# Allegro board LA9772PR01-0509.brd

Outline 275.55 x 178.7 mm; copper layers: TOP, GND1, IN1, VCC, IN2, IN3, GND2, IN4, GND3, BOTTOM. Coordinates in mm from the lower left corner of the outline.

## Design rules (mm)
net group AUDIO: nets PCH_AZ_CODEC_SDIN0 SPKR
net group BLUE_CRT: nets BLUE_CRT BLUE_CRT_L
net group CLK_BUF_DMI: nets CLK_BUF_DMI CLK_BUF_DMI#
net group CLK_CPU_DMI: nets CLK_CPU_DMI CLK_CPU_DMI#
net group CLK_CPU_ITP: nets CLK_CPU_ITP CLK_XDP
net group CLK_CPU_ITP#: nets CLK_CPU_ITP# CLK_XDP#
net group CLK_PCIE_CARD: nets CLK_PCIE_CARD CLK_PCIE_CARD#
net group CLK_PCIE_MINI2: nets CLK_PCIE_MINI2 CLK_PCIE_MINI2#
net group CPU_DPLL: nets CLK_CPU_DPLL CLK_CPU_DPLL#
net group CPU_EDP_AUX: nets CPU_EDP_AUX CPU_EDP_AUX#
net group CPU_EDP_LANE_N0: nets CPU_EDP_LANE_N0 CPU_EDP_LANE_P0
net group CPU_EDP_LANE_N1: nets CPU_EDP_LANE_N1 CPU_EDP_LANE_P1
net group CPU_SSC_DPLL: nets CLK_CPU_SSC_DPLL CLK_CPU_SSC_DPLL#
net group DIFFPAIR0: nets LAN_TX0+ LAN_TX0-
net group DIFFPAIR1: nets PCIE_PRX_WPANTX_N6 PCIE_PRX_WPANTX_P6
net group DIFFPAIR3: nets PCIE_PTX_WPANRX_N6_C PCIE_PTX_WPANRX_P6_C
net group DMI_CTX_PRX_N2: nets DMI_CTX_PRX_N2 DMI_CTX_PRX_P2
net group DP_DDC-DPD_DOCK_AUX: nets DPD_DOCK_AUX DPD_DOCK_AUX#
net group DP_DDC-MB_DP_RP_AUX: nets MB_DP_RP_AUX MB_DP_RP_AUX#
net group DP_DDC-NUX_AUX: nets MUX_AUX MUX_AUX#
net group DP_DPC_DOCK_AUX: nets DPC_DOCK_AUX DPC_DOCK_AUX#
net group DP_DPC_DOCK_SW_AUX: nets DPC_DOCK_SW_AUX DPC_DOCK_SW_AUX#
net group DP_LAN_TX1+R: nets LAN_TX1+R LAN_TX1-R
net group DP_LAN_TX2+R: nets LAN_TX2+R LAN_TX2-R
net group DP_LAN_TX3+R: nets LAN_TX3+R LAN_TX3-R
net group DP_PCH_DDPD_CTRL: nets PCH_DDPD_CTRLCLK PCH_DDPD_CTRLDATA
net group DP_PCIE_PRX_WLANTX_3: nets PCIE_PRX_WLANTX_N3 PCIE_PRX_WLANTX_P3
net group DP_PCIE_PTX_EXPRX_7: nets PCIE_PTX_EXPRX_N7 PCIE_PTX_EXPRX_P7
net group DP_USB3R3: nets USB3RN3 USB3RP3
net group DP_USB3R5: nets USB3RN5 USB3RP5
net group DP_USB3R6: nets USB3RN6 USB3RP6
net group DP_USB3T3: nets USB3TN3 USB3TP3
net group DP_USB3T5: nets USB3TN5 USB3TP5
net group DP_USB3T6: nets USB3TN6 USB3TP6
net group DP_VCC_VSS-SENSE: nets VCCSENSE VSSSENSE
net group DPD_CPU_LANE_N0: nets DPD_CPU_LANE_N0 DPD_CPU_LANE_N0_C
net group DPD_CPU_LANE_N1: nets DPD_CPU_LANE_N1 DPD_CPU_LANE_N1_C
net group DPD_CPU_LANE_N2: nets DPD_CPU_LANE_N2 DPD_CPU_LANE_N2_C
net group DPD_CPU_LANE_N3: nets DPD_CPU_LANE_N3 DPD_CPU_LANE_N3_C
net group DPD_CPU_LANE_P0: nets DPD_CPU_LANE_P0 DPD_CPU_LANE_P0_C
net group DPD_CPU_LANE_P1: nets DPD_CPU_LANE_P1 DPD_CPU_LANE_P1_C
net group DPD_CPU_LANE_P2: nets DPD_CPU_LANE_P2 DPD_CPU_LANE_P2_C
net group DPD_CPU_LANE_P3: nets DPD_CPU_LANE_P3 DPD_CPU_LANE_P3_C
net group ESATA_PRX_DTX_N3_C: nets ESATA_PRX_DTX_N3_C SATA_PRX_DTX_N3
net group ESATA_PRX_DTX_P3_C: nets ESATA_PRX_DTX_P3_C SATA_PRX_DTX_P3
net group ESATA_PTX_DRX_N3_C: nets ESATA_PTX_DRX_N3_C SATA_PTX_DRX_N3
net group ESATA_PTX_DRX_P3_C: nets ESATA_PTX_DRX_P3_C SATA_PTX_DRX_P3
net group FDI-SINGLE: nets FDI_CSYNC FDI_INT
net group GREEN_CRT: nets GREEN_CRT GREEN_CRT_L
net group HDMI_I2C: nets HDMI_SCL_SINK HDMI_SDA_SINK
net group HSYNC: nets HSYNC PCH_CRT_HSYNC
net group HSYNC_BUF: nets HSYNC_BUF HSYNC_L
net group LAN_SMBCLK: nets LAN_SMBCLK LAN_SMBDATA
net group LAN_TX0+: nets LAN_TX0+R LAN_TX0-R
net group LAN_TX1+R: nets LAN_TX1+ LAN_TX1-
net group LAN_TX2+R: nets LAN_TX2+ LAN_TX2-
net group LAN_TX3+R: nets LAN_TX3+ LAN_TX3-
net group MB_DP_RP_C_N0: nets MB_DP_RP_C_N0 MB_DP_RP_N0
net group MB_DP_RP_C_N1: nets MB_DP_RP_C_N1 MB_DP_RP_N1
net group MB_DP_RP_C_N2: nets MB_DP_RP_C_N2 MB_DP_RP_N2
net group MB_DP_RP_C_N3: nets MB_DP_RP_C_N3 MB_DP_RP_N3
net group MB_DP_RP_C_P0: nets MB_DP_RP_C_P0 MB_DP_RP_P0
net group MB_DP_RP_C_P1: nets MB_DP_RP_C_P1 MB_DP_RP_P1
net group MB_DP_RP_C_P2: nets MB_DP_RP_C_P2 MB_DP_RP_P2
net group MB_DP_RP_C_P3: nets MB_DP_RP_C_P3 MB_DP_RP_P3
net group MSATA_PRX_WANTX_N4_RP: nets MSATA_PRX_WANTX_N4_RP MSATA_PRX_WANTX_N4_RP_C
net group MSATA_PRX_WANTX_P4_RP: nets MSATA_PRX_WANTX_P4_RP MSATA_PRX_WANTX_P4_RP_C
net group MSATA_PTX_WANRX_N4_RP: nets MSATA_PTX_WANRX_N4_RP MSATA_PTX_WANRX_N4_RP_C
net group MSATA_PTX_WANRX_P4_RP: nets MSATA_PTX_WANRX_P4_RP MSATA_PTX_WANRX_P4_RP_C
net group MUX_D0: nets MUX_D0 MUX_D0_C
net group MUX_D0#: nets MUX_D0# MUX_D0#_C
net group MUX_D1: nets MUX_D1 MUX_D1_C
net group MUX_D1#: nets MUX_D1# MUX_D1#_C
net group MUX_D2: nets MUX_D2 MUX_D2_C
net group MUX_D2#: nets MUX_D2# MUX_D2#_C
net group MUX_D3: nets MUX_D3 MUX_D3_C
net group MUX_D3#: nets MUX_D3# MUX_D3#_C
net group MXM_DPC_AUX: nets MXM_DPC_AUX MXM_DPC_AUX_C
net group MXM_DPC_AUX#: nets MXM_DPC_AUX# MXM_DPC_AUX#_C
net group MXM_DPC_N0: nets MXM_DPC_N0 MXM_DPC_N0_C
net group MXM_DPC_N1: nets MXM_DPC_N1 MXM_DPC_N1_C
net group MXM_DPC_N2: nets MXM_DPC_N2 MXM_DPC_N2_C
net group MXM_DPC_N3: nets MXM_DPC_N3 MXM_DPC_N3_C
net group MXM_DPC_P0: nets MXM_DPC_P0 MXM_DPC_P0_C
net group MXM_DPC_P1: nets MXM_DPC_P1 MXM_DPC_P1_C
net group MXM_DPC_P2: nets MXM_DPC_P2 MXM_DPC_P2_C
net group MXM_DPC_P3: nets MXM_DPC_P3 MXM_DPC_P3_C
net group MXM_MB_DP_N0: nets MXM_MB_DP_N0 MXM_MB_DP_N0_C
net group MXM_MB_DP_N1: nets MXM_MB_DP_N1 MXM_MB_DP_N1_C
net group MXM_MB_DP_N2: nets MXM_MB_DP_N2 MXM_MB_DP_N2_C
net group MXM_MB_DP_N3: nets MXM_MB_DP_N3 MXM_MB_DP_N3_C
net group MXM_MB_DP_P0: nets MXM_MB_DP_P0 MXM_MB_DP_P0_C
net group MXM_MB_DP_P1: nets MXM_MB_DP_P1 MXM_MB_DP_P1_C
net group MXM_MB_DP_P2: nets MXM_MB_DP_P2 MXM_MB_DP_P2_C
net group MXM_MB_DP_P3: nets MXM_MB_DP_P3 MXM_MB_DP_P3_C
net group PBAT_SMBCLK: nets PBAT_SMBCLK Z4304
net group PBAT_SMBDAT: nets PBAT_SMBDAT Z4305
net group PCH_AZ_BITCLK: nets PCH_AZ_BITCLK PCH_AZ_CODEC_BITCLK
net group PCH_AZ_CODEC_RST#: nets PCH_AZ_CODEC_RST# PCH_AZ_RST#
net group PCH_AZ_CODEC_SDOUT: nets PCH_AZ_CODEC_SDOUT PCH_AZ_SDOUT
net group PCH_AZ_CODEC_SYNC: nets PCH_AZ_CODEC_SYNC PCH_AZ_SYNC
net group PCH_CL_CLK1: nets PCH_CL_CLK1 PCH_CL_DATA1
net group PCH_CRT_VSYNC: nets PCH_CRT_VSYNC VSYNC
net group PCH_DDPD_AUX: nets PCH_DDPD_AUX PCH_DDPD_AUX_C
net group PCH_DDPD_AUX#: nets PCH_DDPD_AUX# PCH_DDPD_AUX#_C
net group PCIE_EXP: nets CLK_PCIE_EXP CLK_PCIE_EXP#
net group PCIE_MINI1: nets CLK_PCIE_MINI1 CLK_PCIE_MINI1#
net group PCIE_PRX_GLANTX_N2: nets PCIE_PRX_GLANTX_N2 PCIE_PRX_GLANTX_N2_C
net group PCIE_PRX_GLANTX_P2: nets PCIE_PRX_GLANTX_P2 PCIE_PRX_GLANTX_P2_C
net group PCIE_PTX_GLANRX_N2: nets PCIE_PTX_GLANRX_N2 PCIE_PTX_GLANRX_N2_C
net group PCIE_PTX_GLANRX_P2: nets PCIE_PTX_GLANRX_P2 PCIE_PTX_GLANRX_P2_C
net group PCIE_PTX_WLANRX_N3: nets PCIE_PTX_WLANRX_N3 PCIE_PTX_WLANRX_N3_C
net group PCIE_PTX_WLANRX_P3: nets PCIE_PTX_WLANRX_P3 PCIE_PTX_WLANRX_P3_C
net group PCIE_SATA_PRX_WANTX_N4: nets PCIE_SATA_PRX_WANTX_N4 PCIE_SATA_PRX_WANTX_N4_C
net group PCIE_SATA_PRX_WANTX_P4: nets PCIE_SATA_PRX_WANTX_P4 PCIE_SATA_PRX_WANTX_P4_C
net group PCIE_SATA_PTX_WANRX_N4: nets PCIE_SATA_PTX_WANRX_N4 PCIE_SATA_PTX_WANRX_N4_C
net group PCIE_SATA_PTX_WANRX_P4: nets PCIE_SATA_PTX_WANRX_P4 PCIE_SATA_PTX_WANRX_P4_C
net group PECI_EC: nets PECI_EC PECI_EC_R
net group PEG_CRX_GTX_C_N0: nets PEG_CRX_GTX_C_N0 PEG_CRX_GTX_N0
net group PEG_CRX_GTX_C_N1: nets PEG_CRX_GTX_C_N1 PEG_CRX_GTX_N1
net group PEG_CRX_GTX_C_N2: nets PEG_CRX_GTX_C_N2 PEG_CRX_GTX_N2
net group PEG_CRX_GTX_C_N3: nets PEG_CRX_GTX_C_N3 PEG_CRX_GTX_N3
net group PEG_CRX_GTX_C_N4: nets PEG_CRX_GTX_C_N4 PEG_CRX_GTX_N4
net group PEG_CRX_GTX_C_N5: nets PEG_CRX_GTX_C_N5 PEG_CRX_GTX_N5
net group PEG_CRX_GTX_C_N6: nets PEG_CRX_GTX_C_N6 PEG_CRX_GTX_N6
net group PEG_CRX_GTX_C_N7: nets PEG_CRX_GTX_C_N7 PEG_CRX_GTX_N7
net group PEG_CRX_GTX_C_N8: nets PEG_CRX_GTX_C_N8 PEG_CRX_GTX_N8
net group PEG_CRX_GTX_C_N9: nets PEG_CRX_GTX_C_N9 PEG_CRX_GTX_N9
net group PEG_CRX_GTX_C_N10: nets PEG_CRX_GTX_C_N10 PEG_CRX_GTX_N10
net group PEG_CRX_GTX_C_N11: nets PEG_CRX_GTX_C_N11 PEG_CRX_GTX_N11
net group PEG_CRX_GTX_C_N12: nets PEG_CRX_GTX_C_N12 PEG_CRX_GTX_N12
net group PEG_CRX_GTX_C_N13: nets PEG_CRX_GTX_C_N13 PEG_CRX_GTX_N13
net group PEG_CRX_GTX_C_N14: nets PEG_CRX_GTX_C_N14 PEG_CRX_GTX_N14
net group PEG_CRX_GTX_C_N15: nets PEG_CRX_GTX_C_N15 PEG_CRX_GTX_N15
net group PEG_CRX_GTX_C_P0: nets PEG_CRX_GTX_C_P0 PEG_CRX_GTX_P0
net group PEG_CRX_GTX_C_P1: nets PEG_CRX_GTX_C_P1 PEG_CRX_GTX_P1
net group PEG_CRX_GTX_C_P2: nets PEG_CRX_GTX_C_P2 PEG_CRX_GTX_P2
net group PEG_CRX_GTX_C_P3: nets PEG_CRX_GTX_C_P3 PEG_CRX_GTX_P3
net group PEG_CRX_GTX_C_P4: nets PEG_CRX_GTX_C_P4 PEG_CRX_GTX_P4
net group PEG_CRX_GTX_C_P5: nets PEG_CRX_GTX_C_P5 PEG_CRX_GTX_P5
net group PEG_CRX_GTX_C_P6: nets PEG_CRX_GTX_C_P6 PEG_CRX_GTX_P6
net group PEG_CRX_GTX_C_P7: nets PEG_CRX_GTX_C_P7 PEG_CRX_GTX_P7
net group PEG_CRX_GTX_C_P8: nets PEG_CRX_GTX_C_P8 PEG_CRX_GTX_P8
net group PEG_CRX_GTX_C_P9: nets PEG_CRX_GTX_C_P9 PEG_CRX_GTX_P9
net group PEG_CRX_GTX_C_P10: nets PEG_CRX_GTX_C_P10 PEG_CRX_GTX_P10
net group PEG_CRX_GTX_C_P11: nets PEG_CRX_GTX_C_P11 PEG_CRX_GTX_P11
net group PEG_CRX_GTX_C_P12: nets PEG_CRX_GTX_C_P12 PEG_CRX_GTX_P12
net group PEG_CRX_GTX_C_P13: nets PEG_CRX_GTX_C_P13 PEG_CRX_GTX_P13
net group PEG_CRX_GTX_C_P14: nets PEG_CRX_GTX_C_P14 PEG_CRX_GTX_P14
net group PEG_CRX_GTX_C_P15: nets PEG_CRX_GTX_C_P15 PEG_CRX_GTX_P15
net group PEG_CTX_GRX_C_N0: nets PEG_CTX_GRX_C_N0 PEG_CTX_GRX_N0
net group PEG_CTX_GRX_C_N1: nets PEG_CTX_GRX_C_N1 PEG_CTX_GRX_N1
net group PEG_CTX_GRX_C_N2: nets PEG_CTX_GRX_C_N2 PEG_CTX_GRX_N2
net group PEG_CTX_GRX_C_N3: nets PEG_CTX_GRX_C_N3 PEG_CTX_GRX_N3
net group PEG_CTX_GRX_C_N4: nets PEG_CTX_GRX_C_N4 PEG_CTX_GRX_N4
net group PEG_CTX_GRX_C_N5: nets PEG_CTX_GRX_C_N5 PEG_CTX_GRX_N5
net group PEG_CTX_GRX_C_N6: nets PEG_CTX_GRX_C_N6 PEG_CTX_GRX_N6
net group PEG_CTX_GRX_C_N7: nets PEG_CTX_GRX_C_N7 PEG_CTX_GRX_N7
net group PEG_CTX_GRX_C_N8: nets PEG_CTX_GRX_C_N8 PEG_CTX_GRX_N8
net group PEG_CTX_GRX_C_N9: nets PEG_CTX_GRX_C_N9 PEG_CTX_GRX_N9
net group PEG_CTX_GRX_C_N10: nets PEG_CTX_GRX_C_N10 PEG_CTX_GRX_N10
net group PEG_CTX_GRX_C_N11: nets PEG_CTX_GRX_C_N11 PEG_CTX_GRX_N11
net group PEG_CTX_GRX_C_N12: nets PEG_CTX_GRX_C_N12 PEG_CTX_GRX_N12
net group PEG_CTX_GRX_C_N13: nets PEG_CTX_GRX_C_N13 PEG_CTX_GRX_N13
net group PEG_CTX_GRX_C_N14: nets PEG_CTX_GRX_C_N14 PEG_CTX_GRX_N14
net group PEG_CTX_GRX_C_N15: nets PEG_CTX_GRX_C_N15 PEG_CTX_GRX_N15
net group PEG_CTX_GRX_C_P0: nets PEG_CTX_GRX_C_P0 PEG_CTX_GRX_P0
net group PEG_CTX_GRX_C_P1: nets PEG_CTX_GRX_C_P1 PEG_CTX_GRX_P1
net group PEG_CTX_GRX_C_P2: nets PEG_CTX_GRX_C_P2 PEG_CTX_GRX_P2
net group PEG_CTX_GRX_C_P3: nets PEG_CTX_GRX_C_P3 PEG_CTX_GRX_P3
net group PEG_CTX_GRX_C_P4: nets PEG_CTX_GRX_C_P4 PEG_CTX_GRX_P4
net group PEG_CTX_GRX_C_P5: nets PEG_CTX_GRX_C_P5 PEG_CTX_GRX_P5
net group PEG_CTX_GRX_C_P6: nets PEG_CTX_GRX_C_P6 PEG_CTX_GRX_P6
net group PEG_CTX_GRX_C_P7: nets PEG_CTX_GRX_C_P7 PEG_CTX_GRX_P7
net group PEG_CTX_GRX_C_P8: nets PEG_CTX_GRX_C_P8 PEG_CTX_GRX_P8
net group PEG_CTX_GRX_C_P9: nets PEG_CTX_GRX_C_P9 PEG_CTX_GRX_P9
net group PEG_CTX_GRX_C_P10: nets PEG_CTX_GRX_C_P10 PEG_CTX_GRX_P10
net group PEG_CTX_GRX_C_P11: nets PEG_CTX_GRX_C_P11 PEG_CTX_GRX_P11
net group PEG_CTX_GRX_C_P12: nets PEG_CTX_GRX_C_P12 PEG_CTX_GRX_P12
net group PEG_CTX_GRX_C_P13: nets PEG_CTX_GRX_C_P13 PEG_CTX_GRX_P13
net group PEG_CTX_GRX_C_P14: nets PEG_CTX_GRX_C_P14 PEG_CTX_GRX_P14
net group PEG_CTX_GRX_C_P15: nets PEG_CTX_GRX_C_P15 PEG_CTX_GRX_P15
net group PSATA_PRX_DTX_N0: nets PSATA_PRX_DTX_N0 PSATA_PRX_DTX_N0_C
net group PSATA_PRX_DTX_P0: nets PSATA_PRX_DTX_P0 PSATA_PRX_DTX_P0_C
net group PSATA_PTX_DRX_N0: nets PSATA_PTX_DRX_N0 PSATA_PTX_DRX_N0_C
net group PSATA_PTX_DRX_P0: nets PSATA_PTX_DRX_P0 PSATA_PTX_DRX_P0_C
net group RED_CRT: nets RED_CRT RED_CRT_L
net group SATA_ODD_PRX_DTX_N1: nets SATA_ODD_PRX_DTX_N1 SATA_ODD_PRX_DTX_N1_C
net group SATA_ODD_PRX_DTX_P1: nets SATA_ODD_PRX_DTX_P1 SATA_ODD_PRX_DTX_P1_C
net group SATA_ODD_PTX_DRX_N1: nets SATA_ODD_PTX_DRX_N1 SATA_ODD_PTX_DRX_N1_C
net group SATA_ODD_PTX_DRX_P1: nets SATA_ODD_PTX_DRX_P1 SATA_ODD_PTX_DRX_P1_C
net group SATA_PRX_DKTX_N2: nets SATA_PRX_DKTX_N2 SATA_PRX_DKTX_N2_C
net group SATA_PRX_DKTX_P2: nets SATA_PRX_DKTX_P2 SATA_PRX_DKTX_P2_C
net group SATA_PTX_DKRX_N2: nets SATA_PTX_DKRX_N2 SATA_PTX_DKRX_N2_C
net group SATA_PTX_DKRX_P2: nets SATA_PTX_DKRX_P2 SATA_PTX_DKRX_P2_C
net group SCLK: nets SCLK VIDSCLK
net group SDA: nets SDA VIDSOUT
net group TMDSE_CON_CLK: nets TMDSE_CON_CLK TMDSE_RP_CLK
net group TMDSE_CON_CLK#: nets TMDSE_CON_CLK# TMDSE_RP_CLK#
net group TMDSE_CON_N0: nets TMDSE_CON_N0 TMDSE_RP_N0
net group TMDSE_CON_N1: nets TMDSE_CON_N1 TMDSE_RP_N1
net group TMDSE_CON_N2: nets TMDSE_CON_N2 TMDSE_RP_N2
net group TMDSE_CON_P0: nets TMDSE_CON_P0 TMDSE_RP_P0
net group TMDSE_CON_P1: nets TMDSE_CON_P1 TMDSE_RP_P1
net group TMDSE_CON_P2: nets TMDSE_CON_P2 TMDSE_RP_P2
net group USB3RN1: nets USB3RN1 USB3RN1_C
net group USB3RN1_RP: nets USB3_RX1_N_D- USB3RN1_RP
net group USB3RN2: nets USB3RN2 USB3RN2_C
net group USB3RN2_RP: nets USB3_RX2_N_D- USB3RN2_RP
net group USB3RP1: nets USB3RP1 USB3RP1_C
net group USB3RP1_RP: nets USB3_RX1_P_D+ USB3RP1_RP
net group USB3RP2: nets USB3RP2 USB3RP2_C
net group USB3RP2_RP: nets USB3_RX2_P_D+ USB3RP2_RP
net group USB3TN1: nets USB3TN1 USB3TN1_C
net group USB3TN2: nets USB3TN2 USB3TN2_C
net group USB3TP1: nets USB3TP1 USB3TP1_C
net group USB3TP2: nets USB3TP2 USB3TP2_C
net group USBP0_D+: nets USBP0_D+ USBP0_R_D+
net group USBP0_D-: nets USBP0_D- USBP0_R_D-
net group USBP1+: nets USBP1+ USBP1_D+
net group USBP1-: nets USBP1- USBP1_D-
net group USBP8+: nets USBP8+ USBP8_D+
net group USBP8-: nets USBP8- USBP8_D-
net group USBP12+: nets USBP12+ USBP12_D+
net group USBP12-: nets USBP12- USBP12_D-
net group VSYNC_BUF: nets VSYNC_BUF VSYNC_L
net group ALERT#: nets ALERT# H_CPU_SVIDALRT# VIDALERT_N
net group ASYNCHRONOUS: nets DDR3_DRAMRST#_CPU DDR3_DRAMRST#_R DDR_HVREF_RST_PCH H_CATERR# H_CPUPWRGD H_CPUPWRGD_XDP H_PM_SYNC H_PROCHOT# H_PROCHOT#_R H_THERMTRIP# PCH_JTAG_TCK PCH_JTAG_TMS PCH_PLTRST# PCH_PLTRST#_EC PM_DRAM_PWRGD RUNPWROK THERMATRIP2# XDP_RST#_R XDP_TCLK
net group ASYNCHRONOUS-S15: nets PEG_COMP
net group ASYNCHRONOUS-S20: nets DMI_RCOMP
net group CLK-SINGLE: nets CLK_PCH_14M
net group CLK-SINGLE-S15: nets CLK_80H CLK_PCI_LOOPBACK CLK_PCI_TPM CLK_SIO_14M JETWAY_14M JETWAY_CLK14M PCI_LOOPBACKOUT PCI_TPM_TCM PCLK_80H SIO_14M
net group CLK_SRC: nets CLK_PCIE_LAN CLK_PCIE_LAN# CLK_PCIE_MINI3 CLK_PCIE_MINI3# CLK_PCIE_VGA CLK_PCIE_VGA#
net group CONTROL LINK: nets PCH_CL_RST1#
net group CRT-DAC: nets BLUE_DOCK GREEN_DOCK MXM_CRT_BLU MXM_CRT_GRN MXM_CRT_RED PCH_CRT_BLU PCH_CRT_GRN PCH_CRT_RED RED_DOCK
net group CRT-SINGLE: nets CLK_DDC2_CRT CLK_DDC2_DOCK DAT_DDC2_CRT DAT_DDC2_DOCK
net group CRT-SYNC: nets HSYNC_DOCK MXM_CRT_HSYNC MXM_CRT_VSYNC VSYNC_DOCK
net group DDR_XDP_SMBCLK_R1: nets DDR_XDP_SMBCLK_R1 DDR_XDP_WAN_SMBCLK DDR_XDP_WAN_SMBCLK_R2
net group DDR_XDP_SMBDAT_R1: nets DDR_XDP_SMBDAT_R1 DDR_XDP_WAN_SMBDAT DDR_XDP_WAN_SMBDAT_R2
net group DDRA_D0: nets DDR_A_D0 DDR_A_D1 DDR_A_D4 DDR_A_D5
net group DDRA_D1: nets DDR_A_D10 DDR_A_D11 DDR_A_D12 DDR_A_D13
net group DDRA_D2: nets DDR_A_D16 DDR_A_D17 DDR_A_D18 DDR_A_D19 DDR_A_D20 DDR_A_D21 DDR_A_D22 DDR_A_D23
net group DDRA_D3: nets DDR_A_D24 DDR_A_D25 DDR_A_D26 DDR_A_D27 DDR_A_D28 DDR_A_D29 DDR_A_D30 DDR_A_D31
net group DDRA_D4: nets DDR_A_D32 DDR_A_D33 DDR_A_D36 DDR_A_D37
net group DDRA_D5: nets DDR_A_D40 DDR_A_D41 DDR_A_D42 DDR_A_D43 DDR_A_D44 DDR_A_D45 DDR_A_D46 DDR_A_D47
net group DDRA_D6: nets DDR_A_D50 DDR_A_D51 DDR_A_D54
net group DDRA_D7: nets DDR_A_D56 DDR_A_D57 DDR_A_D60 DDR_A_D61 DDR_A_D62 DDR_A_D63
net group DDRB_D0: nets DDR_B_D0 DDR_B_D1 DDR_B_D2 DDR_B_D3 DDR_B_D4 DDR_B_D5 DDR_B_D6 DDR_B_D7
net group DDRB_D1: nets DDR_B_D8 DDR_B_D9 DDR_B_D10 DDR_B_D12 DDR_B_D13 DDR_B_D14
net group DDRB_D2: nets DDR_B_D16 DDR_B_D17 DDR_B_D18 DDR_B_D19 DDR_B_D20 DDR_B_D21 DDR_B_D22 DDR_B_D23
net group DDRB_D3: nets DDR_B_D24 DDR_B_D25 DDR_B_D26 DDR_B_D27 DDR_B_D28 DDR_B_D29 DDR_B_D30 DDR_B_D31
net group DDRB_D4: nets DDR_B_D32 DDR_B_D33 DDR_B_D34 DDR_B_D35 DDR_B_D36 DDR_B_D37 DDR_B_D38 DDR_B_D39
net group DDRB_D5: nets DDR_B_D40 DDR_B_D41 DDR_B_D42 DDR_B_D43 DDR_B_D44 DDR_B_D45
net group DDRB_D6: nets DDR_B_D50 DDR_B_D51 DDR_B_D54 DDR_B_D55
net group DDRB_D7: nets DDR_B_D56 DDR_B_D57 DDR_B_D58 DDR_B_D59 DDR_B_D62 DDR_B_D63
net group DPC_DOCK_LANE_C_N0: nets DPC_DOCK_LANE_C_N0 DPC_DOCK_LANE_N0_R MXM_DPB_N0
net group DPC_DOCK_LANE_C_N1: nets DPC_DOCK_LANE_C_N1 DPC_DOCK_LANE_N1_R MXM_DPB_N1
net group DPC_DOCK_LANE_C_N2: nets DPC_DOCK_LANE_C_N2 DPC_DOCK_LANE_N2_R MXM_DPB_N2
net group DPC_DOCK_LANE_C_N3: nets DPC_DOCK_LANE_C_N3 DPC_DOCK_LANE_N3_R MXM_DPB_N3
net group DPC_DOCK_LANE_C_P0: nets DPC_DOCK_LANE_C_P0 DPC_DOCK_LANE_P0_R MXM_DPB_P0
net group DPC_DOCK_LANE_C_P1: nets DPC_DOCK_LANE_C_P1 DPC_DOCK_LANE_P1_R MXM_DPB_P1
net group DPC_DOCK_LANE_C_P2: nets DPC_DOCK_LANE_C_P2 DPC_DOCK_LANE_P2_R MXM_DPB_P2
net group DPC_DOCK_LANE_C_P3: nets DPC_DOCK_LANE_C_P3 DPC_DOCK_LANE_P3_R MXM_DPB_P3
net group DPD_DOCK_LANE_N0: nets DPD_DOCK_LANE_N0 DPD_DOCK_LANE_N0_R DPD_GPU_LANE_N0
net group DPD_DOCK_LANE_N1: nets DPD_DOCK_LANE_N1 DPD_DOCK_LANE_N1_R DPD_GPU_LANE_N1
net group DPD_DOCK_LANE_N2: nets DPD_DOCK_LANE_N2 DPD_DOCK_LANE_N2_R DPD_GPU_LANE_N2
net group DPD_DOCK_LANE_N3: nets DPD_DOCK_LANE_N3 DPD_DOCK_LANE_N3_R DPD_GPU_LANE_N3
net group DPD_DOCK_LANE_P0: nets DPD_DOCK_LANE_P0 DPD_DOCK_LANE_P0_R DPD_GPU_LANE_P0
net group DPD_DOCK_LANE_P1: nets DPD_DOCK_LANE_P1 DPD_DOCK_LANE_P1_R DPD_GPU_LANE_P1
net group DPD_DOCK_LANE_P2: nets DPD_DOCK_LANE_P2 DPD_DOCK_LANE_P2_R DPD_GPU_LANE_P2
net group DPD_DOCK_LANE_P3: nets DPD_DOCK_LANE_P3 DPD_DOCK_LANE_P3_R DPD_GPU_LANE_P3
net group EDP: nets CPU_EDP_AUX#_C CPU_EDP_AUX_C CPU_EDP_LANE_N0_C CPU_EDP_LANE_N1_C CPU_EDP_LANE_P0_C CPU_EDP_LANE_P1_C LCD_EDP_AUX LCD_EDP_AUX# LCD_EDP_AUX#_C LCD_EDP_AUX_C LCD_EDP_LANE_N0 LCD_EDP_LANE_N0_C LCD_EDP_LANE_N1 LCD_EDP_LANE_N1_C LCD_EDP_LANE_N2 LCD_EDP_LANE_N2_C LCD_EDP_LANE_N3 LCD_EDP_LANE_N3_C LCD_EDP_LANE_P0 LCD_EDP_LANE_P0_C LCD_EDP_LANE_P1 LCD_EDP_LANE_P1_C LCD_EDP_LANE_P2 LCD_EDP_LANE_P2_C LCD_EDP_LANE_P3 LCD_EDP_LANE_P3_C
net group FDI_DP: nets FDI_CTX_PRX_N0 FDI_CTX_PRX_N1 FDI_CTX_PRX_P0 FDI_CTX_PRX_P1
net group LVDS_MUX-LVDS_CONN: nets MXM_EDP_HPD
net group MXM-EDP: nets MXM_EDP_AUX MXM_EDP_AUX# MXM_EDP_AUX#_C MXM_EDP_AUX_C MXM_EDP_LANE_N0 MXM_EDP_LANE_N0_C MXM_EDP_LANE_N1 MXM_EDP_LANE_N1_C MXM_EDP_LANE_N2 MXM_EDP_LANE_N2_C MXM_EDP_LANE_N3 MXM_EDP_LANE_N3_C MXM_EDP_LANE_P0 MXM_EDP_LANE_P0_C MXM_EDP_LANE_P1 MXM_EDP_LANE_P1_C MXM_EDP_LANE_P2 MXM_EDP_LANE_P2_C MXM_EDP_LANE_P3 MXM_EDP_LANE_P3_C
net group MXM_MB_DP_AUX: nets MXM_MB_DP_AUX_C
net group MXM_MB_DP_AUX#: nets MXM_MB_DP_AUX#_C
net group PCIE: nets PCIE_PRX_EXPTX_N7 PCIE_PRX_EXPTX_P7 PCIE_PRX_MMITX_N8 PCIE_PRX_MMITX_P8 PCIE_PTX_MMIRX_N8 PCIE_PTX_MMIRX_P8 PCIE_PTX_WPANRX_N6 PCIE_PTX_WPANRX_P6
net group RTC: nets PCH_RTCRST# PCH_RTCX1 PCH_RTCX2 SRTCRST#
net group SM_RCOMP: nets CFG_RCOMP SM_RCOMP0 SM_RCOMP1 SM_RCOMP2
net group SMB: nets CARD_SMBCLK CARD_SMBDAT CHARGER_SMBCLK CHARGER_SMBDAT DOCK_SMB_CLK DOCK_SMB_DAT GPU_SMBCLK GPU_SMBCLK_R GPU_SMBDAT GPU_SMBDAT_R LCD_SMBCLK LCD_SMBCLK_Q LCD_SMBDAT LCD_SMBDAT_Q MEM_SMBCLK MEM_SMBDATA SML1_SMBCLK SML1_SMBDATA USH_SMBCLK USH_SMBDAT
net group SPACING-15: nets SATA_COMP
net group SPACING-20: nets CLK_PCI_5048 CLK_PCI_DOCK CLK_PCI_MEC FDI_RCOMP PCH_PCIE_RCOMP PCI_5048 PCI_DOCK PCI_MEC
net group SPACING-25: nets EDP_COMP
net group SPI: nets PCH_SPI_CS0# PCH_SPI_CS1# PCH_SPI_DIN PCH_SPI_DO PCH_SPI_DO2 PCH_SPI_DO3 SPI_DIN32 SPI_DIN64 SPI_DO32 SPI_DO64 SPI_PCH_CS0# SPI_PCH_CS0#_R SPI_PCH_CS1# SPI_PCH_CS1#_R SPI_PCH_DIN SPI_PCH_DO SPI_PCH_DO2 SPI_PCH_DO2_32 SPI_PCH_DO2_64 SPI_PCH_DO3 SPI_PCH_DO3_32 SPI_PCH_DO3_64
net group SPI-CLK: nets PCH_SPI_CLK SPI_CLK32 SPI_CLK64 SPI_PCH_CLK
net group THERMAL: nets REM_DIODE1_N REM_DIODE1_N_4021 REM_DIODE1_P REM_DIODE1_P_4021 REM_DIODE2_N REM_DIODE2_N_4021 REM_DIODE2_P REM_DIODE2_P_4021 REM_DIODE3_N REM_DIODE3_P REM_DIODE4_N REM_DIODE4_P
net group USB2.0: nets USBP0+ USBP0- USBP2+ USBP2- USBP3+ USBP3- USBP4+ USBP4- USBP5+ USBP5- USBP7+ USBP7-
net group USB3TN1_RP: nets USB3_TX1_N_D- USB3TN1_RP USB3TN1_RP_C
net group USB3TN2_RP: nets USB3_TX2_N_D- USB3TN2_RP USB3TN2_RP_C
net group USB3TP1_RP: nets USB3_TX1_P_D+ USB3TP1_RP USB3TP1_RP_C
net group USB3TP2_RP: nets USB3_TX2_P_D+ USB3TP2_RP USB3TP2_RP_C
net group USB-SINGLE: nets USBRBIAS
nets with their own width: min track width 0.254; nets +3.3V_SPI CSSN_1 CSSP_1
nets with their own width: min track width 0.381; nets SOFT_START_GC
nets with their own width: min track width 0.508; nets +1.05V_MP +1.5V_RUN +1.5V_RUNP +3.3V_ALW2 +3.3V_ALW_PCH +3.3V_ALW_PCH_JTAG +3.3V_LAN_OUT +3.3V_MXM +3.3V_RTC_LDO +5V_ALW2 +5V_MOD +ADDR_XEN +CAP_LDO +CHAGER_SRC +COINCELL +DC1_PWR_SRC +DC_IN +DC_IN_SS +DCIN_JACK +DOCK_PWR_BAR +LOM_VCT +NBDOCK_DC_IN_SS +PCH_VCCDSW +PECI_VREF +PWR_SRC_S +RSVD_VCC3P3_2 +RTC_CELL +SDC_IN +SIM_PWR +TRM_CT1 +TRM_CT2 +TRM_CT3 +TRM_CT4 +VCC_CORE +VCCADAC +VCHGR +VR_CAP GND REGCTL_PNP10
nets with their own width: min track width 1.016; nets +1.05V_M +3.3V_ALW_U46 +3.3V_LAN +3.3V_M +3.3V_RUN_TPM +3.3V_SUS +CAMERA_VDD +CRT_VCC +VDISPLAY_VCC
nets with their own width: min track width 1.524; nets +3.3V_RUN
nets with their own width: min track width 2.032; nets +1.05V_RUN +3.3V_WLAN +5V_ALW +5V_HDD +5V_RUN +5V_USB_PWR1 +5V_USB_PWR2 +BL_PWR_SRC +LCDVDD +PWR_SRC +PWR_SRC_MXM +V_DDR_REF
nets with their own width: min track width 2.54; nets +5V_ESATA_PWR +5V_MXM
nets with their own width: min track width 3.048; nets +3.3V_ALW
nets with their own width: min track width 10.16; nets +MXM_PWR_SRC

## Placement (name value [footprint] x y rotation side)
C1  -  [C_0603]  130.27 108.62 180 top
C2  -  [C_0805]  130.55 111.42 180 top
C3  -  [C_0603]  130.27 109.89 180 top
C4  -  [C_0402]  130.03 107.48 180 top
C7  -  [C_0402]  122.21 107.66 90 top
C8  -  [C_0402]  55.58 96.3 0 bottom
C14  -  [C_0402]  79.97 166.28 0 top
C15  -  [C_0402]  81.87 166.28 0 top
C16  -  [C_0402]  82.42 134.21 0 bottom
C20  -  [C_0402]  72.54 164.78 270 top
C22  -  [C_0402]  77.17 164.81 180 top
C23  -  [C_0402]  74.01 164.82 0 top
C45  -  [C_0402]  169.54 115.94 90 bottom
C46  -  [C_0402]  23.83 162.34 0 bottom
C47  -  [C_0805]  21.84 163.99 180 bottom
C48  -  [C_0402]  159.13 116.06 90 bottom
C52  -  [C_0402]  54.57 6.41 90 bottom
C53  -  [C_0402]  53.03 6.44 90 bottom
C56  -  [C_0402]  55.51 6.41 90 bottom
C86  -  [C_0402]  26.63 163.87 0 top
C87  -  [C_0402]  235.94 91.4 90 bottom
C88  -  [C_0402]  238.43 79.28 180 bottom
C90  -  [C_0402]  81.06 102.07 90 bottom
C95  -  [C_0402]  65.81 98.89 0 bottom
C97  -  [C_0402]  30.31 149.77 0 top
C98  -  [C_0402]  60.3 137.45 180 top
C119  -  [C_0603]  250.03 84.24 180 bottom
C248  -  [C_0402]  49.49 149.64 0 bottom
C249  -  [C_0603]  54.52 154.79 180 top
C271  -  [C_0402]  171.05 128.81 180 top
C272  -  [C_0402]  123.91 63.28 0 bottom
C273  -  [C_0402]  91.09 114.03 270 top
C278  -  [C_0402]  164.63 131.15 180 top
C279  -  [C_0402]  57.44 110.2 90 top
C280  -  [C_0402]  60.99 110.2 90 top
C281  -  [C_0402]  59.22 110.2 90 top
C282  -  [C_0402]  58.33 110.2 90 top
C283  -  [C_0402]  61.88 110.2 90 top
C284  -  [C_0402]  63.66 110.2 90 top
C285  -  [C_0402]  62.77 110.2 90 top
C286  -  [C_0402]  60.11 110.2 90 top
C287  -  [C_0402]  163.48 138.9 90 top
C288  -  [C_0402]  55.71 42.14 0 bottom
C289  -  [C_0402]  141.42 142.57 270 top
C290  -  [C_0402]  147.33 140.46 180 top
C291  -  [C_0402]  85 141.31 90 bottom
C295  -  [C_0402]  247.13 84.81 180 bottom
C296  -  [C_0603]  51.28 153.83 180 bottom
C297  -  [C_1206]  55.77 157.16 180 bottom
C298  -  [C_0402]  48.42 152.39 270 bottom
C299  -  [C_0402]  53.5 151.92 90 top
C300  -  [C_0805]  54.9 151.46 90 top
C301  -  [C_0402]  57.48 149.35 0 bottom
C302  -  [C_0402]  247.13 89.25 180 bottom
C303  -  [C_0402]  247.13 88.36 180 bottom
C304  -  [C_0402]  247.13 83.92 180 bottom
C306  -  [C_0402]  247.13 86.59 180 bottom
C307  -  [C_0402]  247.13 83.03 180 bottom
C308  -  [C_0402]  247.13 85.7 180 bottom
C309  -  [C_0402]  247.13 87.48 180 bottom
C313  -  [C_0402]  260.83 157.2 180 bottom
C315  -  [C_0402]  173.9 131.72 90 top
C318  -  [C_0402]  173.95 137.58 0 top
C319  -  [C_0402]  173.9 133.56 90 top
C323  -  [C_D2]  259.67 132.86 270 bottom
C324  -  [C_D2]  259.46 116.99 90 bottom
C327  -  [C_0402]  159.67 137.15 270 top
C328  -  [C_0603]  123.35 107.67 90 top
C329  -  [C_0805]  12.12 133.25 180 top
C330  -  [C_0805]  172.54 141.5 180 top
C332  -  [C_0603]  55.34 97.45 0 bottom
C335  -  [C_0402]  55.71 43.09 0 bottom
C339  -  [C_0402]  89.11 53.5 0 top
C340  -  [C_0402]  118.27 71.79 0 top
C356  -  [C_0805]  126.98 110.63 90 bottom
C357  -  [C_0805]  53.49 77.54 0 bottom
C358  -  [C_0805]  84.27 139.53 180 bottom
C359  -  [C_0402]  71.6 112.16 90 top
C360  -  [C_0805]  122.11 111.44 180 bottom
C361  -  [C_0805]  46.94 33.69 90 top
C364  -  [C_0402]  14 132.19 90 bottom
C366  -  [C_0402]  74.14 111.3 270 bottom
C367  -  [C_0402]  75.15 111.3 270 bottom
C368  -  [C_0402]  76.17 111.3 270 bottom
C369  -  [C_0402]  77.19 111.3 270 bottom
C370  -  [C_0402]  172.59 142.82 180 top
C371  -  [C_0402]  54.07 143.04 180 top
C372  -  [C_0402]  54.09 140.37 180 top
C373  -  [C_0402]  54.07 142.15 180 top
C374  -  [C_0402]  54.09 141.26 180 top
C375  -  [C_0402]  54.09 138.59 180 top
C376  -  [C_0402]  54.09 139.48 180 top
C377  -  [C_0402]  54.09 136.82 180 top
C378  -  [C_0402]  54.09 137.7 180 top
C379  -  [C_0402]  54.09 135.04 180 top
C380  -  [C_0402]  54.09 135.93 180 top
C383  -  [C_0402]  167.81 50.26 180 top
C384  -  [C_0402]  167.81 51.15 180 top
C385  -  [C_0402]  167.72 53.76 270 top
C386  -  [C_0402]  166.84 53.76 270 top
C387  -  [C_0402]  81.31 113.12 90 top
C388  -  [C_0402]  81.31 115.15 90 top
C391  -  [C_0402]  172.22 41.87 0 bottom
C392  -  [C_0603]  166.54 41.57 180 bottom
C395  -  [C_0402]  168.84 69.12 180 bottom
C397  -  [C_0402]  240.89 79.4 90 bottom
C398  -  [C_0402]  241.78 79.4 90 bottom
C402  -  [C_0402]  16.11 154.6 180 top
C403  -  [C_0402]  167.55 61.19 180 top
C404  -  [C_0402]  167.55 62.08 180 top
C405  -  [C_0402]  19.85 160.77 270 bottom
C406  -  [C_0402]  168.84 70.01 180 bottom
C410  -  [C_0402]  25.89 159.68 180 bottom
C424  -  [C_0402]  78.2 111.3 270 bottom
C425  -  [C_0402]  79.22 111.3 270 bottom
C426  -  [C_0402]  80.23 111.3 270 bottom
C427  -  [C_0402]  81.25 111.3 270 bottom
C428  -  [C_0402]  39.28 34.53 270 top
C429  -  [C_0402]  40.17 34.53 270 top
C430  -  [C_0402]  39.23 44.23 0 top
C431  -  [C_0402]  73.95 135.85 90 bottom
C432  -  [C_0402]  39.23 45.38 0 top
C433  -  [C_0402]  39.23 49.19 0 top
C434  -  [C_0402]  39.23 48.04 0 top
C435  -  [C_0402]  52.71 108.21 270 bottom
C436  -  [C_0402]  123.17 108.47 0 bottom
C437  -  [C_0402]  24.29 153.33 90 bottom
C438  -  [C_0402]  74.96 135.85 90 bottom
C439  -  [C_0402]  75.98 135.85 90 bottom
C440  -  [C_0402]  77 135.85 90 bottom
C441  -  [C_0402]  78.01 135.85 90 bottom
C442  -  [C_0402]  79.03 135.85 90 bottom
C443  -  [C_0402]  80.04 135.85 90 bottom
C444  -  [C_0402]  81.06 135.85 90 bottom
C449  -  [C_0805]  53.67 112.56 0 bottom
C450  -  [C_0402]  233.08 90.05 90 bottom
C452  -  [C_0402]  228.7 82.93 270 bottom
C453  -  [C_0402]  234 90.08 0 bottom
C454  -  [C_0402]  229.59 82.93 270 bottom
C456  -  [C_0402]  231.56 83 270 bottom
C457  -  [C_0402]  232.44 83 270 bottom
C458  -  [C_0402]  117.2 148.12 180 bottom
C459  -  [C_0402]  117.2 149.01 180 bottom
C460  -  [C_0402]  116.29 150.02 0 bottom
C461  -  [C_0402]  116.29 150.91 0 bottom
C462  -  [C_0603]  125.83 153.2 180 top
C463  -  [C_0402]  119.08 153.33 0 top
C464  -  [C_0603]  123.35 147.93 90 top
C465  -  [C_0402]  231.11 81.16 270 bottom
C466  -  [C_0402]  125.59 152.06 180 top
C467  -  [C_0402]  119.08 148.88 0 top
C468  -  [C_0402]  125.59 149.64 180 top
C469  -  [C_0402]  123.48 154.29 270 top
C470  -  [C_0402]  126.15 157.57 90 bottom
C471  -  [C_0402]  126.15 156.7 270 bottom
C472  -  [C_0402]  130.97 140.57 270 top
C473  -  [C_0402]  127.92 140.57 270 top
C474  -  [C_0402]  128.94 136.61 90 top
C478  -  [C_0402]  129.07 146.67 270 top
C479  -  [C_0603]  159.29 142.59 270 top
C480  -  [C_0603]  160.56 142.59 270 top
C481  -  [C_0603]  152.05 166.72 90 bottom
C482  -  [C_0805]  261.22 155.8 180 bottom
C483  -  [C_0402]  153.2 166.71 90 bottom
C484  -  [C_0603]  167.04 142.72 270 top
C485  -  [C_1808]  174.02 146.2 90 top
C486  -  [C_0603]  168.31 142.72 270 top
C487  -  [C_0402]  230.22 81.16 270 bottom
C488  -  [C_0402]  228 91 270 bottom
C489  -  [C_0402]  228.89 91 270 bottom
C490  -  [C_0402]  233.02 81.16 270 bottom
C491  -  [C_0402]  233.9 81.16 270 bottom
C492  -  [C_0402]  231.3 91 270 bottom
C493  -  [C_0402]  232.19 91 270 bottom
C494  -  [C_0402]  31.23 148.88 180 top
C495  -  [C_0402]  38.95 159.17 0 top
C496  -  [C_0402]  245.47 79.73 180 bottom
C497  -  [C_0402]  240.64 91.4 90 bottom
C499  -  [C_0402]  37.83 148.63 180 bottom
C502  -  [C_0402]  60.3 135.67 180 top
C503  -  [C_0402]  65.92 146.62 90 top
C504  -  [C_0402]  31.23 156.88 180 top
C505  -  [C_0402]  25.69 164.83 270 top
C506  -  [C_0402]  24.8 164.83 270 top
C507  -  [C_0402]  31.23 150.66 180 top
C508  -  [C_0402]  31.23 151.55 180 top
C509  -  [C_0402]  31.23 152.44 180 top
C510  -  [C_0402]  31.23 153.33 180 top
C511  -  [C_0402]  31.23 155.1 180 top
C512  -  [C_0402]  31.23 155.99 180 top
C513  -  [C_0402]  212.43 64.55 0 bottom
C514  -  [C_0402]  212.43 63.66 0 bottom
C515  -  [C_0402]  44.62 154.47 180 top
C516  -  [C_0402]  44.62 155.36 180 top
C517  -  [C_0402]  42.15 155.23 180 top
C518  -  [C_0402]  42.15 156.12 180 top
C519  -  [C_0402]  44.62 157.14 180 top
C520  -  [C_0402]  44.62 158.02 180 top
C521  -  [C_0402]  42.15 157.77 180 top
C522  -  [C_0402]  42.15 158.66 180 top
C523  -  [C_0402]  42.15 147.74 180 top
C524  -  [C_0402]  42.15 148.63 180 top
C525  -  [C_0402]  42.15 149.52 180 top
C526  -  [C_0402]  42.15 150.4 180 top
C527  -  [C_0402]  42.15 151.29 180 top
C528  -  [C_0402]  42.15 152.18 180 top
C529  -  [C_0402]  42.15 153.07 180 top
C530  -  [C_0402]  42.15 153.96 180 top
C531  -  [C_0402]  34.96 161.15 270 top
C532  -  [C_0402]  35.85 161.15 270 top
C533  -  [C_0402]  212.43 66.33 0 bottom
C534  -  [C_0402]  212.43 65.44 0 bottom
C535  -  [C_0402]  33.18 161.15 270 top
C536  -  [C_0402]  34.07 161.15 270 top
C537  -  [C_0402]  222.61 66.84 180 bottom
C538  -  [C_0402]  222.61 65.95 180 bottom
C539  -  [C_0402]  222.61 65.06 180 bottom
C540  -  [C_0402]  222.61 64.17 180 bottom
C541  -  [C_0402]  51.23 78.2 180 bottom
C542  -  [C_0402]  80.67 139.88 0 bottom
C543  -  [C_0402]  123.17 109.36 0 bottom
C544  -  [C_0402]  44.69 34.81 90 top
C545  -  [C_0402]  122.6 167.33 90 top
C546  -  [C_0402]  263.88 59.23 270 bottom
C547  -  [C_0402]  116.53 147.23 0 bottom
C548  -  [C_0402]  14.21 109.51 180 bottom
C549  -  [C_0402]  43.75 34.83 90 top
C550  -  [C_0402]  159.13 112.66 270 bottom
C551  -  [C_0402]  160.14 116.06 90 bottom
C552  -  [C_0402]  169.54 112.66 270 bottom
C553  -  [C_0402]  160.14 112.66 270 bottom
C554  -  [C_0402]  122.37 165.02 90 top
C555  -  [C_0402]  44.89 149.21 270 bottom
C556  -  [C_0402]  70.83 135.02 180 top
C557  -  [C_0402]  70.83 134.11 180 top
C558  -  [C_0402]  67.47 133.53 270 top
C559  -  [C_0402]  70.85 136.88 180 top
C560  -  [C_0402]  60.13 142.29 180 top
C561  -  [C_0402]  70.83 135.96 180 top
C562  -  [C_0402]  70.85 140.58 180 top
C563  -  [C_0402]  70.85 142.44 180 top
C564  -  [C_0402]  70.85 139.67 180 top
C565  -  [C_0402]  70.85 141.52 180 top
C566  -  [C_0402]  64.11 147.55 270 top
C567  -  [C_0402]  70.9 144.28 180 top
C568  -  [C_0402]  64.99 147.55 270 top
C569  -  [C_0402]  63.21 147.54 270 top
C570  -  [C_0402]  62.33 147.55 270 top
C571  -  [C_0402]  70.85 138.73 180 top
C572  -  [C_0402]  70.9 143.4 180 top
C573  -  [C_0402]  70.85 137.82 180 top
C593  -  [C_0402]  249.28 67.47 180 bottom
C594  -  [C_0402]  249.28 75.22 180 bottom
C595  -  [C_0402]  147.66 144.56 0 bottom
C596  -  [C_0402]  132.67 153.71 0 bottom
C598  -  [C_0402]  132.67 154.6 0 bottom
C604  -  [C_0402]  132.75 156.93 90 bottom
C605  -  [C_0402]  133.64 156.93 90 bottom
C606  -  [C_0402]  147.61 151.88 270 bottom
C607  -  [C_0402]  148.62 162.98 180 bottom
C608  -  [C_0603]  131.61 156.69 90 bottom
C610  -  [C_0402]  263.36 70.41 0 bottom
C611  -  [C_0402]  263.36 71.3 0 bottom
C612  -  [C_0402]  249.28 76.24 180 bottom
C613  -  [C_0805]  249.11 66.08 180 bottom
C614  -  [C_0402]  250.1 88.25 270 bottom
C615  -  [C_0805]  250.34 91.07 90 bottom
C616  -  [C_0402]  240.95 35.9 90 bottom
C617  -  [C_0402]  250.1 85.56 90 bottom
C624  -  [C_0402]  99.03 135.08 270 top
C626  -  [C_0402]  101.76 134.21 90 top
C628  -  [C_0402]  244.64 35.9 90 bottom
C629  -  [C_0402]  242.22 35.9 90 bottom
C630  -  [C_0402]  243.49 35.9 90 bottom
C631  -  [C_0402]  245.53 35.9 90 bottom
C633  -  [C_0603]  116.19 142.28 90 top
C634  -  [C_0402]  94.1 142.24 90 top
C636  -  [C_0402]  102.66 134.21 90 top
C637  -  [C_0402]  104.77 140.85 0 top
C638  -  [C_0402]  117.29 143.23 270 top
C639  -  [C_0402]  98.14 135.08 270 top
C667  -  [C_D2]  64.33 160.77 0 bottom
C668  -  [C_0402]  65.27 165.48 270 top
C669  -  [C_0805]  257.12 96.18 0 bottom
C670  -  [C_0402]  257.51 97.57 0 bottom
C671  -  [C_0402]  39.91 166.03 90 top
C672  -  [C_0402]  40.93 166.03 90 top
C673  -  [C_0402]  42.96 166.03 90 top
C674  -  [C_0402]  43.98 166.03 90 top
C675  -  [C_0402]  67.9 161.71 0 top
C676  -  [C_0805]  67.51 160.31 0 top
C695  -  [C_0402]  82.83 117.83 0 top
C696  -  [C_0402]  82.63 125.77 0 top
C697  -  [C_0402]  87.79 125.82 90 top
C698  -  [C_0402]  88.68 125.82 90 top
C699  -  [C_0402]  89.57 126.73 270 top
C700  -  [C_0402]  90.46 126.73 270 top
C702  -  [C_0603]  125.19 126.02 270 top
C703  -  [C_0603]  123.8 126.02 270 top
C704  -  [C_0402]  106.21 118.81 270 top
C708  -  [C_0402]  207.12 75.02 270 bottom
C709  -  [C_0402]  219.06 88.8 90 bottom
C710  -  [C_0402]  210.08 77.4 180 bottom
C712  -  [C_0402]  208.14 84.62 180 bottom
C713  -  [C_0402]  208.14 82.33 180 bottom
C714  -  [C_0603]  215.81 90.9 90 bottom
C715  -  [C_0402]  258.42 108.46 270 bottom
C716  -  [C_0402]  223.55 92.06 270 bottom
C717  -  [C_0402]  208.01 75.02 270 bottom
C718  -  [C_0402]  208.9 75.02 270 bottom
C719  -  [C_0402]  226.02 80.68 0 bottom
C721  -  [C_0402]  4.73 79.54 180 top
C722  -  [C_0402]  15.73 72.12 270 top
C723  -  [C_0402]  15.91 111.11 270 top
C724  -  [C_0402]  16.34 87.03 0 top
C725  -  [C_0402]  16.34 85.89 0 top
C734  -  [C_0402]  107.35 163.41 90 top
C735  -  [C_0402]  103.29 164.3 90 bottom
C736  -  [C_0402]  104.68 166.08 90 bottom
C737  -  [C_0402]  105.89 148.89 270 bottom
C739  -  [C_0402]  104.89 148.88 180 bottom
C740  -  [C_0402]  98.33 164.3 90 bottom
C741  -  [C_0402]  109.81 165.45 0 bottom
C742  -  [C_0402]  113.5 155.23 0 bottom
C743  -  [C_0402]  108.95 165.45 180 bottom
C744  -  [C_0402]  109.33 155.74 180 top
C746  -  [C_0402]  52.36 93.56 90 bottom
C747  -  [C_0402]  101.44 146.54 270 bottom
C756  -  [C_0402]  182.47 112.51 270 top
C757  -  [C_0402]  104.68 164.3 90 bottom
C758  -  [C_0402]  182.47 113.5 90 top
C760  -  [C_0603]  54.22 107.54 0 bottom
C761  -  [C_0603]  123.96 168.06 90 top
C763  -  [C_0402]  3.98 72.17 180 top
C764  -  [C_0603]  267.5 59.15 270 bottom
C765  -  [C_0603]  116.56 146.16 0 bottom
C766  -  [C_0603]  26.01 158.53 180 bottom
C767  -  [C_0603]  41.31 34.52 270 top
C769  -  [C_0603]  47.47 153.83 0 bottom
C770  -  [C_0603]  124.05 162.71 0 top
C772  -  [C_0603]  38.64 123.42 270 top
C773  -  [C_0402]  37.89 127.54 0 top
C774  -  [C_0402]  149.74 109.7 90 top
C776  -  [C_1206]  139.61 107.16 270 top
C777  -  [C_0402]  96.38 151.8 180 bottom
C779  -  [C_0603]  111.86 154.6 0 top
C780  -  [C_0402]  101.25 164.3 90 bottom
C781  -  [C_0402]  96 156.5 180 bottom
C782  -  [C_0603]  95.03 148.44 270 bottom
C783  -  [C_0603]  40.99 159.8 0 top
C784  -  [C_0603]  67.53 146.64 90 top
C793  -  [C_0603]  259.81 105.51 270 top
C794  -  [C_0603]  259.81 135.67 180 bottom
C1167  -  [C_0402]  154.21 166.71 90 bottom
C1174  -  [C_0402]  81.31 131.86 270 top
C1176  -  [C_D2E]  265.72 68.05 270 bottom
C1177  -  [C_0805]  119.33 151.04 0 top
C1178  -  [C_0805]  120.68 159.46 90 top
C1179  -  [C_D2E]  265.71 75.68 90 bottom
C1180  -  [C_0402]  173.95 138.47 0 top
C1181  -  [C_0402]  87.79 155.15 90 bottom
C1182  -  [C_0603]  79.03 159.61 90 bottom
C1216  -  [C_0402]  59.65 89.95 0 bottom
C1312  -  [C_0402]  215.93 61.33 270 bottom
C1313  -  [C_0402]  215.05 61.33 270 bottom
C1332  -  [C_0402]  24.1 150.35 270 top
C1333  -  [C_0402]  19.24 165.75 180 top
C1334  -  [C_0402]  20.17 165.77 0 top
C1335  -  [C_0402]  17.4 164.56 0 top
C1336  -  [C_0402]  16.52 164.56 180 top
C1337  -  [C_0402]  15.33 165.9 0 top
C1338  -  [C_0402]  14.45 165.91 180 top
C1339  -  [C_0402]  11.76 165.68 0 top
C1340  -  [C_0402]  10.93 165.69 180 top
C1341  -  [C_0402]  242.86 91.4 90 bottom
C1343  -  [C_0402]  108.29 154.21 0 top
C1345  -  [C_0402]  111.21 155.23 0 bottom
C1346  -  [C_0402]  112.05 152.39 270 bottom
C1347  -  [C_0402]  106.78 148.89 270 bottom
C1348  -  [C_0402]  103.03 148.83 270 bottom
C1349  -  [C_0402]  104.89 147.99 180 bottom
C1350  -  [C_0402]  108.29 153.33 0 top
C1351  -  [C_0402]  109.2 152.44 180 top
C1352  -  [C_0402]  108.75 163.41 90 top
C1353  -  [C_0402]  106.66 161.2 180 top
C1355  -  [C_0402]  108.37 159.6 90 top
CC1  -  [C_0402]  114.33 107.72 90 top
CC2  -  [C_0402]  112.56 107.72 90 top
CC3  -  [C_0402]  110.78 107.72 90 top
CC4  -  [C_0402]  109 107.72 90 top
CC5  -  [C_0402]  107.22 107.72 90 top
CC6  -  [C_0402]  105.44 107.72 90 top
CC7  -  [C_0402]  103.67 107.72 90 top
CC8  -  [C_0402]  101.89 107.72 90 top
CC9  -  [C_0402]  100.11 107.72 90 top
CC10  -  [C_0402]  98.33 107.72 90 top
CC11  -  [C_0402]  96.55 107.72 90 top
CC12  -  [C_0402]  94.78 107.72 90 top
CC13  -  [C_0402]  93 107.72 90 top
CC14  -  [C_0402]  91.16 107.72 90 top
CC15  -  [C_0402]  89.38 107.72 90 top
CC16  -  [C_0402]  87.6 107.72 90 top
CC17  -  [C_0402]  113.45 107.72 90 top
CC18  -  [C_0402]  111.67 107.72 90 top
CC19  -  [C_0402]  109.89 107.72 90 top
CC20  -  [C_0402]  108.11 107.72 90 top
CC21  -  [C_0402]  106.33 107.72 90 top
CC22  -  [C_0402]  104.56 107.72 90 top
CC23  -  [C_0402]  102.78 107.72 90 top
CC24  -  [C_0402]  101 107.72 90 top
CC25  -  [C_0402]  99.22 107.72 90 top
CC26  -  [C_0402]  97.44 107.72 90 top
CC27  -  [C_0402]  95.67 107.72 90 top
CC28  -  [C_0402]  93.89 107.72 90 top
CC29  -  [C_0402]  92.11 107.72 90 top
CC30  -  [C_0402]  90.27 107.72 90 top
CC31  -  [C_0402]  88.49 107.72 90 top
CC32  -  [C_0402]  86.71 107.72 90 top
CC33  -  [C_0805]  94.23 63.28 180 bottom
CC34  -  [C_0805]  94.23 67.35 180 top
CC35  -  [C_0805]  94.23 63.28 180 top
CC36  -  [C_0805]  94.23 65.44 180 top
CC37  -  [C_0805]  94.23 59.22 180 bottom
CC38  -  [C_0805]  94.23 65.44 180 bottom
CC39  -  [C_0805]  94.23 57.06 180 top
CC40  -  [C_0805]  94.23 61.25 180 top
CC41  -  [C_0805]  94.23 57.06 180 bottom
CC42  -  [C_0805]  94.23 61.25 180 bottom
CC43  -  [C_0805]  94.23 59.22 180 top
CC44  -  [C_0402]  114.33 94.6 270 top
CC45  -  [C_0402]  112.56 94.6 270 top
CC46  -  [C_0402]  107.22 94.6 270 top
CC47  -  [C_0402]  103.67 94.6 270 top
CC48  -  [C_0402]  98.33 94.6 270 top
CC49  -  [C_0402]  93.51 94.6 270 top
CC50  -  [C_0402]  88.05 94.6 270 top
CC51  -  [C_0402]  109.89 94.6 270 top
CC52  -  [C_0402]  108.11 94.6 270 top
CC53  -  [C_0402]  110.78 94.6 270 top
CC54  -  [C_0402]  104.56 94.6 270 top
CC55  -  [C_0402]  102.78 94.6 270 top
CC56  -  [C_0402]  101.89 94.6 270 top
CC57  -  [C_0402]  99.22 94.6 270 top
CC58  -  [C_0402]  97.44 94.6 270 top
CC59  -  [C_0402]  96.81 92.82 270 top
CC60  -  [C_0402]  94.4 94.6 270 top
CC61  -  [C_0402]  92.62 94.6 270 top
CC62  -  [C_0402]  91.73 94.6 270 top
CC63  -  [C_0402]  88.93 94.6 270 top
CC64  -  [C_0402]  87.16 94.6 270 top
CC65  -  [C_0402]  73.06 11.9 90 bottom
CC66  -  [C_0603]  72.36 16.86 90 bottom
CC67  -  [C_0402]  113.45 94.6 270 top
CC68  -  [C_0402]  111.67 94.6 270 top
CC69  -  [C_0402]  106.33 94.6 270 top
CC70  -  [C_0402]  101 94.6 270 top
CC71  -  [C_0402]  95.92 92.82 270 top
CC72  -  [C_0402]  90.84 94.6 270 top
CC73  -  [C_0402]  109 94.59 270 top
CC74  -  [C_0402]  105.44 94.6 270 top
CC75  -  [C_0402]  100.11 94.6 270 top
CC76  -  [C_0402]  95.28 94.6 270 top
CC77  -  [C_0402]  89.82 94.6 270 top
CC78  -  [C_0805]  67.05 71.79 180 bottom
CC79  -  [C_0805]  67.05 73.57 180 bottom
CC137  -  [C_0603]  86.52 33.88 90 top
CC138  -  [C_0402]  113.45 85.68 180 bottom
CC161  -  [C_0805]  94.23 55.15 180 top
CC162  -  [C_0805]  94.23 53.38 180 top
CC163  -  [C_0805]  94.23 55.15 180 bottom
CC164  -  [C_0805]  94.23 48.04 180 bottom
CC165  -  [C_0805]  94.23 48.04 180 top
CC166  -  [C_0805]  94.23 49.82 180 top
CC167  -  [C_D2]  89.57 49.41 90 bottom
CC168  -  [C_0805]  94.23 49.82 180 bottom
CC169  -  [C_0805]  94.23 51.6 180 top
CC170  -  [C_0805]  94.23 53.38 180 bottom
CC171  -  [C_0805]  94.23 51.6 180 bottom
CC172  -  [C_D2]  108.64 34.32 270 bottom
CD1  -  [C_0603]  130.21 87.6 270 top
CD2  -  [C_0402]  131.35 87.11 270 top
CD3  -  [C_0402]  132.97 56.49 180 top
CD4  -  [C_0402]  132.84 64.81 180 top
CD5  -  [C_0402]  132.97 59.03 180 top
CD6  -  [C_0402]  132.97 54.01 180 top
CD7  -  [C_0603]  132.7 66.01 180 top
CD8  -  [C_0603]  132.76 63.6 180 top
CD9  -  [C_0603]  132.83 60.27 180 top
CD10  -  [C_0603]  132.83 57.76 180 top
CD11  -  [C_0603]  132.83 55.22 180 top
CD12  -  [C_0603]  132.89 52.8 180 top
CD13  -  [C_0603]  132.89 51.28 180 top
CD14  -  [C_APXK2R5ARA331MF451]  165.08 48.07 90 top
CD15  -  [C_0402]  125.24 30.68 90 top
CD16  -  [C_0402]  126.13 30.68 90 top
CD17  -  [C_0402]  127.02 30.68 90 top
CD18  -  [C_0402]  127.91 30.68 90 top
CD19  -  [C_0603]  132.5 48.61 270 top
CD20  -  [C_0402]  131.35 48.12 270 top
CD21  -  [C_0402]  131.81 33.44 180 top
CD22  -  [C_0603]  132.05 34.58 180 top
CD23  -  [C_0402]  131.35 87.11 270 bottom
CD24  -  [C_0402]  132.97 54.01 180 bottom
CD25  -  [C_0402]  132.84 64.81 180 bottom
CD26  -  [C_0603]  130.21 87.6 270 bottom
CD27  -  [C_0402]  132.97 59.03 180 bottom
CD28  -  [C_0402]  132.97 56.49 180 bottom
CD29  -  [C_0603]  132.76 63.6 180 bottom
CD30  -  [C_0603]  132.83 57.76 180 bottom
CD31  -  [C_0603]  132.83 55.22 180 bottom
CD32  -  [C_0603]  132.89 52.8 180 bottom
CD33  -  [C_0603]  132.7 66.01 180 bottom
CD34  -  [C_0603]  132.83 60.27 180 bottom
CD35  -  [C_0603]  132.89 51.28 180 bottom
CD36  -  [C_APXK2R5ARA331MF451]  165.01 66.02 270 top
CD37  -  [C_0402]  121.69 30.68 90 top
CD38  -  [C_0402]  122.58 30.68 90 top
CD39  -  [C_0402]  123.47 30.68 90 top
CD40  -  [C_0402]  124.35 30.68 90 top
CD41  -  [C_0603]  132.5 48.61 270 bottom
CD42  -  [C_0402]  131.35 48.12 270 bottom
CD43  -  [C_0402]  132.06 33.44 180 bottom
CD44  -  [C_0603]  132.05 34.58 180 bottom
CD45  -  [C_0402]  181.01 91.08 90 bottom
CD46  -  [C_0402]  182.03 91.08 90 bottom
CD47  -  [C_0402]  162.66 64.6 0 top
CD48  -  [C_0402]  164.04 62.27 0 top
CD49  -  [C_0402]  164.04 59.98 0 top
CD50  -  [C_0402]  164.04 57.69 0 top
CD51  -  [C_0603]  163.8 52.11 0 top
CD52  -  [C_0603]  163.8 63.41 0 top
CD53  -  [C_0603]  163.8 61.12 0 top
CD54  -  [C_0603]  163.8 58.84 0 top
CD55  -  [C_0603]  163.8 56.55 0 top
CD56  -  [C_0603]  163.79 55.15 0 top
CD57  -  [C_0603]  163.79 53.63 0 top
CD58  -  [C_APXK2R5ARA331MF451]  165.16 76.45 270 top
CD59  -  [C_0402]  165.13 28.92 90 bottom
CD60  -  [C_0402]  166.02 28.92 90 bottom
CD61  -  [C_0402]  166.91 28.92 90 bottom
CD62  -  [C_0402]  167.8 28.92 90 bottom
CD63  -  [C_0603]  163.42 47.41 180 bottom
CD64  -  [C_0402]  161.96 49.39 270 bottom
CD65  -  [C_0402]  162.77 27.98 0 top
CD66  -  [C_0603]  166.53 32.48 90 bottom
CD67  -  [C_0402]  164.04 65.19 0 bottom
CD68  -  [C_0402]  164.04 62.65 0 bottom
CD69  -  [C_0402]  164.04 60.36 0 bottom
CD70  -  [C_0402]  164.04 57.95 0 bottom
CD71  -  [C_0603]  183.17 87.35 90 bottom
CD72  -  [C_0402]  184.21 87.18 90 bottom
CD73  -  [C_0603]  163.79 61.5 0 bottom
CD74  -  [C_0603]  163.79 53.63 0 bottom
CD75  -  [C_0603]  163.79 66.33 0 bottom
CD76  -  [C_0603]  163.79 63.92 0 bottom
CD77  -  [C_0603]  163.79 56.68 0 bottom
CD78  -  [C_0603]  163.79 59.09 0 bottom
CD79  -  [C_0603]  163.79 55.15 0 bottom
CD80  -  [C_APXK2R5ARA331MF451]  165.38 37.25 180 top
CD81  -  [C_0402]  168.69 28.92 90 bottom
CD82  -  [C_0402]  171.36 28.92 90 bottom
CD83  -  [C_0402]  170.47 28.92 90 bottom
CD84  -  [C_0402]  169.58 28.92 90 bottom
CD85  -  [C_0603]  163.8 50.46 0 bottom
CD86  -  [C_0402]  163.79 51.6 0 bottom
CD87  -  [C_0402]  162.77 28.87 0 top
CD88  -  [C_0603]  165.26 32.48 90 bottom
CD89  -  [C_0402]  125.26 84.75 180 top
CD90  -  [C_0402]  126.27 48.12 270 top
CD91  -  [C_0402]  178.98 87.21 90 bottom
CE1  -  [C_0402]  47.79 94.98 270 bottom
CE2  -  [C_0402]  53.96 95.41 180 bottom
CE3  -  [C_0402]  159.05 114.74 0 bottom
CE8  -  [C_0402]  97.06 112.23 90 bottom
CE9  -  [C_0402]  91.98 112.23 90 bottom
CH2  -  [C_0402]  21.05 118.58 90 bottom
CH4  -  [C_0402]  23.28 92 270 bottom
CH5  -  [C_0402]  23.99 88.43 180 bottom
CH6  -  [C_0402]  19.01 93.51 0 bottom
CH7  -  [C_0402]  19.01 93.64 0 top
CH9  -  [C_0402]  16.72 101.13 0 top
CH13  -  [C_0402]  38.69 112.94 0 top
CH14  -  [C_0402]  41.39 112.94 180 top
CH15  -  [C_0402]  20.94 109.26 180 bottom
CH16  -  [C_0402]  22.51 112.89 270 top
CH17  -  [C_0402]  46.95 86.14 0 top
CH18  -  [C_0402]  30.95 109.76 0 bottom
CH19  -  [C_0402]  31.33 108.75 0 bottom
CH20  -  [C_0603]  30.9 110.72 90 bottom
CH21  -  [C_0603]  36.83 117.64 0 bottom
CH22  -  [C_0402]  37.19 98.08 180 bottom
CH23  -  [C_0402]  30.51 105.12 90 bottom
CH24  -  [C_0402]  13.62 102.83 90 bottom
CH25  -  [C_0402]  38.74 103.77 0 bottom
CH26  -  [C_0603]  44.17 105.19 0 bottom
CH27  -  [C_0402]  30.82 102.84 0 bottom
CH28  -  [C_0805]  33.35 112.43 0 bottom
CH29  -  [C_0402]  33.1 99.05 90 bottom
CH30  -  [C_0402]  29.37 96.86 90 bottom
CH31  -  [C_0603]  44.17 102.53 0 bottom
CH32  -  [C_0603]  46.44 98.49 180 bottom
CH33  -  [C_0603]  43.05 101.81 90 bottom
CH34  -  [C_0402]  32.6 101.51 0 bottom
CH35  -  [C_0402]  34.5 98.08 0 bottom
CH36  -  [C_0402]  38.88 99.03 0 bottom
CH37  -  [C_0402]  38.02 99.03 180 bottom
CH38  -  [C_0603]  39.21 117.64 0 bottom
CH39  -  [C_0402]  33.47 96.42 180 bottom
CH40  -  [C_0402]  29.87 95.1 90 bottom
CH41  -  [C_0603]  33.94 109.32 270 bottom
CH42  -  [C_0402]  35.92 99.86 180 bottom
CH43  -  [C_0402]  31.15 99.86 180 bottom
CH44  -  [C_0402]  19.08 91.68 270 bottom
CH45  -  [C_0402]  36.15 101.51 0 bottom
CH46  -  [C_0402]  34.12 94.98 270 bottom
CH47  -  [C_0402]  37.19 96.68 180 bottom
CH48  -  [C_0402]  37.04 102.53 0 bottom
CH49  -  [C_0402]  35.42 96.43 180 bottom
CH50  -  [C_0402]  22.89 119.21 90 bottom
CH51  -  [C_0402]  30.39 98.21 135 bottom
CH52  -  [C_0603]  46.58 100.11 180 bottom
CH53  -  [C_0402]  25.18 100.11 180 bottom
CH54  -  [C_0402]  30.82 96.43 0 bottom
CH55  -  [C_0402]  17.69 91.3 270 bottom
CH56  -  [C_0402]  16.8 91.3 270 bottom
CH57  -  [C_0402]  14.45 92.26 180 bottom
CH58  -  [C_0402]  30.72 114.84 180 bottom
CH59  -  [C_0402]  34.96 91.3 270 bottom
CH60  -  [C_0402]  42.58 94.78 270 bottom
CH61  -  [C_0402]  44.36 94.79 270 bottom
CH62  -  [C_0402]  43.47 94.79 270 bottom
CH63  -  [C_0603]  43.98 111.99 90 top
CH64  -  [C_0402]  42.83 111.97 90 top
CH65  -  [C_0402]  35.92 95.16 180 bottom
CH66  -  [C_0402]  18.58 102.45 90 bottom
CH67  -  [C_0402]  34.12 119.42 0 bottom
CH68  -  [C_0402]  34.12 118.53 0 bottom
CH69  -  [C_0402]  34.12 120.31 0 bottom
CH70  -  [C_0402]  33.94 104.1 90 bottom
CH71  -  [C_0402]  34.37 101.51 0 bottom
CH72  -  [C_0402]  28.74 101.33 270 bottom
CH73  -  [C_0402]  29.85 102.35 270 bottom
CH74  -  [C_0402]  30.82 101.51 0 bottom
CH75  -  [C_0402]  18.58 105.14 270 bottom
CH76  -  [C_0402]  20.94 108.37 180 bottom
CH77  -  [C_0402]  20.35 96.43 180 top
CH78  -  [C_0402]  18.02 110.27 180 top
CH79  -  [C_0402]  21.57 105.32 180 bottom
CH80  -  [C_0402]  19.97 106.51 90 bottom
CH93  -  [C_B2]  40.7 111.8 180 bottom
CMOS1  -  [SHORTPADS]  68.41 24.34 270 bottom
D6  -  [BAT54CW_SOT323-3]  44.48 146 180 bottom
D7  -  [DB2J31400L_SOD323-2]  59.82 105.83 0 bottom
D8  -  [DB2J31400L_SOD323-2]  58.06 106.07 270 bottom
D14  -  [TVWDF1004AD0_DFN9]  259.35 112.13 90 top
D15  -  [L30ESDL5V0C3-2_SOT23-3]  258.33 112.62 90 bottom
D16  -  [TVWDF1004AD0_DFN9]  260.18 129.43 180 top
D17  -  [L30ESDL5V0C3-2_SOT23-3]  264.55 124.14 270 top
D18  -  [DB2J31400L_SOD323-2]  59.82 104.05 0 bottom
D21  -  [PESD5V0U2BT_SOT23-3]  56.04 148.69 90 top
D22  -  [PESD5V0U2BT_SOT23-3]  58.41 153.25 180 top
D29  -  [RB751S40T1G_SOD523-2]  149.39 152.63 90 bottom
D30  -  [RB751S40T1G_SOD523-2]  131.58 159.55 90 top
D31  -  [RB751S40T1G_SOD523-2]  148.82 147.74 180 bottom
D32  -  [RB751S40T1G_SOD523-2]  108.11 126.4 180 top
D33  -  [L30ESD24VC3-2_SOT23-3]  121.07 123.9 0 top
D53  -  [DB2J31400L_SOD323-2]  42.23 144.56 180 bottom
D59  -  [RB751S40T1G_SOD523-2]  11.72 152.25 270 top
D62  -  [RB751S40T1G_SOD523-2]  11.85 147.61 90 top
D64  -  [DB2J31400L_SOD323-2]  44.32 139.1 0 bottom
D66  -  [DB2J31400L_SOD323-2]  53.63 150.01 90 bottom
D67  -  [DB2J31400L_SOD323-2]  43.5 141.26 180 bottom
D68  -  [DB2J31400L_SOD323-2]  49.82 146.41 90 bottom
D69  -  [DB2J31400L_SOD323-2]  45.47 142.53 0 bottom
D71  -  [DB2J31400L_SOD323-2]  48.17 146.41 90 bottom
D73  -  [L30ESDL5V0C3-2_SOT23-3]  35.75 165.14 90 top
D88  -  [L30ESDL5V0C3-2_SOT23-3]  78.77 131.35 0 top
D90  -  [RB751S40T1G_SOD523-2]  171.48 139.74 0 top
D91  -  [BAT1000-7-F_SOT23-3]  259.95 146.38 0 bottom
F3  -  [F_1206L150THWR]  261.66 153.87 180 bottom
FD1  -  [FIDUCIAL_C40M80]  272.87 147.64 180 bottom
FD2  -  [FIDUCIAL_C40M80]  75.85 2.96 180 bottom
FD3  -  [FIDUCIAL_C40M80]  272.87 147.64 0 top
FD4  -  [FIDUCIAL_C40M80]  75.85 2.96 0 top
H1  -  [H_3P2X6P2N]  11.95 158.81 0 top
H2  -  [H_2P8]  28.95 171.3 0 top
H3  -  [H_3P3]  47.82 162.8 0 top
H4  -  [H_2P3]  56.95 173.8 0 top
H5  -  [H_3P8]  56.72 165.93 0 top
H7  -  [H_3P8]  131.72 165.93 0 top
H8  -  [H_3P8]  162.75 125.93 0 top
H9  -  [H_2P8]  188.95 105 0 top
H10  -  [H_2P8]  264.95 100.3 0 top
